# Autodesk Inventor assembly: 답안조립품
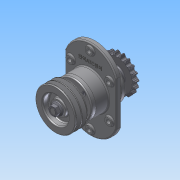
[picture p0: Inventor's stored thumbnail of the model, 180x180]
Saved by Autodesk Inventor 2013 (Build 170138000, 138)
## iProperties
Created: 2015-02
Part Number: 답안조립품
Document SubType Name: Assembly
Designer: ST5
Author: ST5
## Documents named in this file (11)
- C:\Users\ST5\Desktop\450207V1012\답안조립품.iam
- C:\Users\ST5\Desktop\450207V1012\1 본체.ipt
- C:\Users\ST5\Desktop\450207V1012\3-축.ipt
- C:\Users\ST5\Desktop\450207V1012\11-키 6x6.ipt
- C:\Users\ST5\Desktop\450207V1012\2-커버.ipt
- C:\Users\ST5\Desktop\450207V1012\10-M6.ipt
- C:\Users\ST5\Desktop\450207V1012\8-오일실 30x42.ipt
- C:\Users\ST5\Desktop\450207V1012\6-베어링 6206.ipt
- C:\Users\ST5\Desktop\450207V1012\4-V벨트풀리.ipt
- C:\Users\ST5\Desktop\450207V1012\9-M16-너트.ipt
- C:\Users\ST5\Desktop\450207V1012\5-체인 스프로킷.ipt
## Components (22 placed, 10 different names)
1. 1 본체:1 — 각도:3, 각도:4, 각도:5
2. 3-축:1 — 각도:1, 각도:2
3. 11-키 6x6:1 — 각도:1, 각도:5
4. 11-키 6x6:2 — 각도:2
5. 2-커버:1 — 플러쉬:1
6. 2-커버:2 — 플러쉬:2
7. 8-8-오일실 30x42:1 — 플러쉬:1
8. 8-8-오일실 30x42:2 — 플러쉬:2
9. 6-베어링 6206:1
10. 6-베어링 6206:2
11. 4-V벨트풀리:1
12. 9-M16 너트:1 — 각도:3
13. 5-체인 스프로킷:1
14. 9-M16 너트:2 — 각도:4
15. 10-M6:1
16. 10-M6:2
17. 10-M6:3
18. 10-M6:4
19. 10-M6:5
20. 10-M6:6
21. 10-M6:7
22. 10-M6:8
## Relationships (7: Angle 5, Flush 2)
- 각도:1 [Angle]: 3-축:1 ↔ 11-키 6x6:1
- 각도:2 [Angle]: 3-축:1 ↔ 11-키 6x6:2
- 플러쉬:1 [Flush]: 2-커버:1 ↔ 8-8-오일실 30x42:1
- 플러쉬:2 [Flush]: 2-커버:2 ↔ 8-8-오일실 30x42:2
- 각도:3 [Angle]: 1 본체:1 ↔ 9-M16 너트:1
- 각도:4 [Angle]: 1 본체:1 ↔ 9-M16 너트:2
- 각도:5 [Angle]: 1 본체:1 ↔ 11-키 6x6:1
